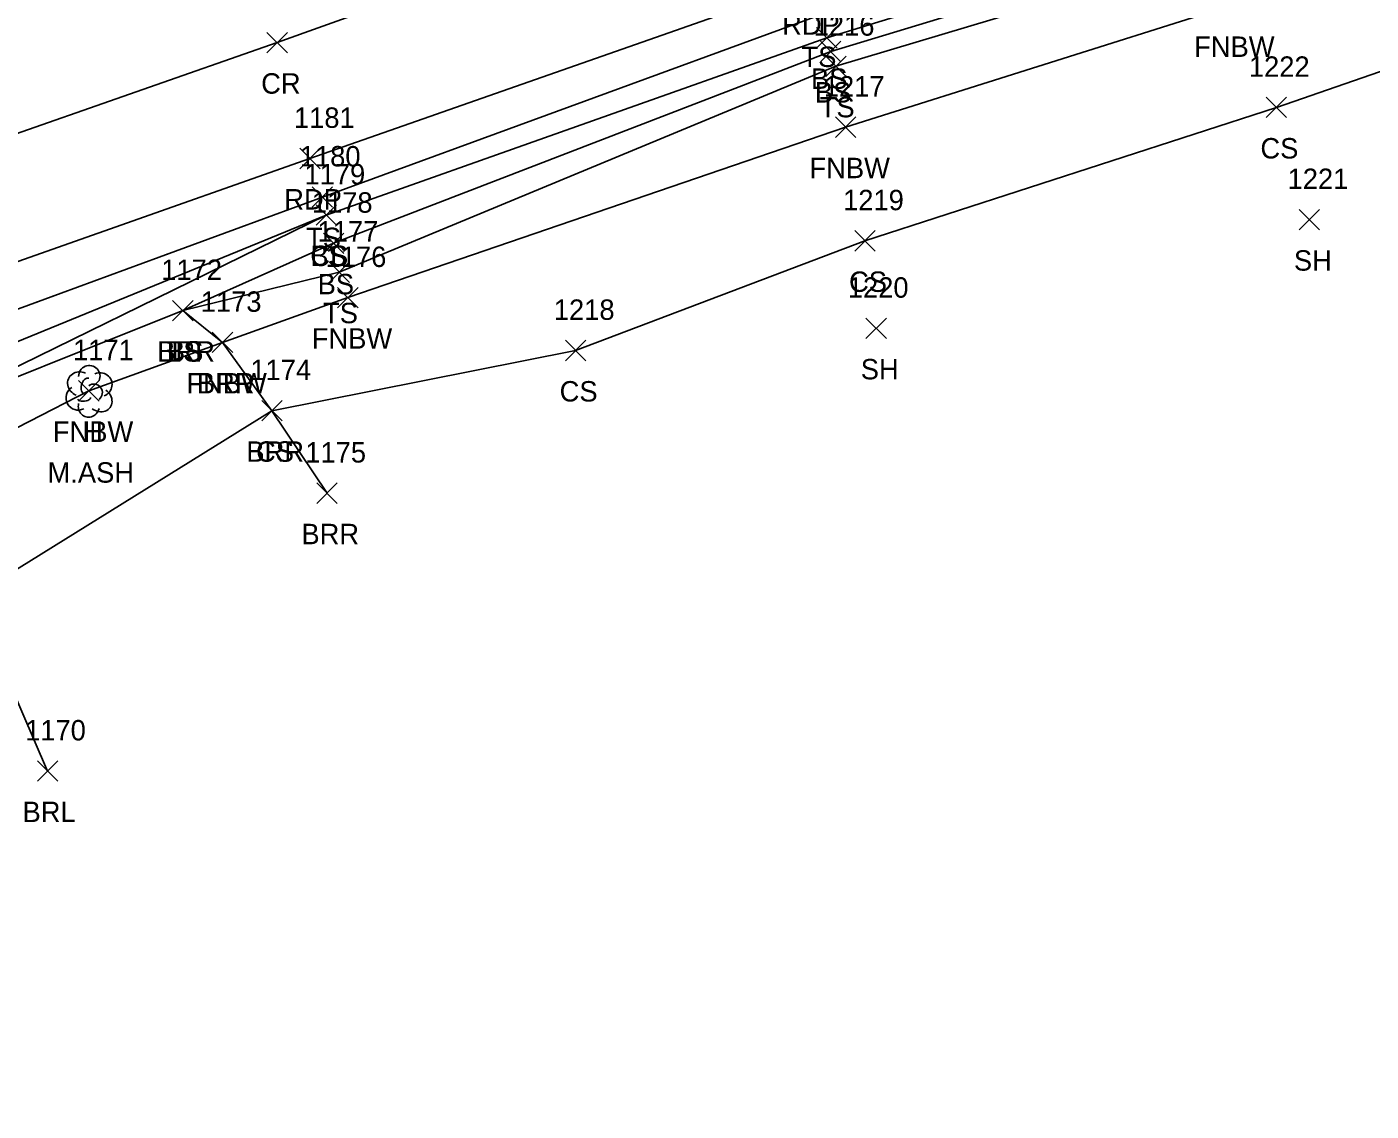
# Model space of a CAD drawing. Extents: x 1443064 to 1445163, y 544063 to 544655.
# Drawn here: x 1443332.1 to 1443463.7, y 544086.5 to 544192.7 of the extents above; entities that cross this region are included whole.
import ezdxf

# ---------------------------------------------------------------- set-up
doc = ezdxf.new("R2010")
doc.units = 0
for name, color, linetype in [('L_A', 7, 'Continuous'), ('L_C', 7, 'Continuous'), ('L_I', 7, 'Continuous'), ('L_TIC', 7, 'Continuous'), ('LABL', 7, 'Continuous'), ('LELB', 7, 'Continuous'), ('LFNC', 7, 'Continuous'), ('LTD', 7, 'Continuous'), ('P_A', 7, 'Continuous'), ('P_I', 7, 'Continuous'), ('P_TIC', 7, 'Continuous'), ('PET', 7, 'Continuous'), ('PRC', 7, 'Continuous')]:
    doc.layers.add(name, color=color, linetype=linetype)

msp = doc.modelspace()

# ---------------------------------------------------------------- linework, layer by layer
at = {"layer": 'L_TIC'}
for points in [[(1443409.41, 544190.66), (1443411.41, 544192.66)], [(1443411.41, 544190.66), (1443409.41, 544192.66)], [(1443409.79, 544189.32), (1443411.79, 544191.32)], [(1443411.79, 544189.32), (1443409.79, 544191.32)], [(1443410.3, 544187.87), (1443412.3, 544189.87)], [(1443412.3, 544187.87), (1443410.3, 544189.87)], [(1443453.43, 544183.84), (1443455.43, 544185.84)], [(1443455.43, 544183.84), (1443453.43, 544185.84)], [(1443411.24, 544181.91), (1443413.24, 544183.91)], [(1443413.24, 544181.91), (1443411.24, 544183.91)], [(1443360, 544175.06), (1443362, 544177.06)], [(1443362, 544175.06), (1443360, 544177.06)], [(1443360.38, 544173.3), (1443362.38, 544175.3)], [(1443362.38, 544173.3), (1443360.38, 544175.3)], [(1443360.38, 544173.3), (1443362.38, 544175.3)], [(1443362.38, 544173.3), (1443360.38, 544175.3)], [(1443456.66, 544172.85), (1443458.66, 544174.85)], [(1443458.66, 544172.85), (1443456.66, 544174.85)], [(1443361.1, 544170.53), (1443363.1, 544172.53)], [(1443363.1, 544170.53), (1443361.1, 544172.53)], [(1443413.14, 544170.77), (1443415.14, 544172.77)], [(1443415.14, 544170.77), (1443413.14, 544172.77)], [(1443361.66, 544167.7), (1443363.66, 544169.7)], [(1443363.66, 544167.7), (1443361.66, 544169.7)], [(1443362.5, 544165.21), (1443364.5, 544167.21)], [(1443364.5, 544165.21), (1443362.5, 544167.21)], [(1443346.34, 544163.94), (1443348.34, 544165.94)], [(1443348.34, 544163.94), (1443346.34, 544165.94)], [(1443346.34, 544163.94), (1443348.34, 544165.94)], [(1443348.34, 544163.94), (1443346.34, 544165.94)], [(1443346.34, 544163.94), (1443348.34, 544165.94)], [(1443348.34, 544163.94), (1443346.34, 544165.94)], [(1443414.24, 544162.2), (1443416.24, 544164.2)], [(1443416.24, 544162.2), (1443414.24, 544164.2)], [(1443350.22, 544160.82), (1443352.22, 544162.82)], [(1443352.22, 544160.82), (1443350.22, 544162.82)], [(1443350.22, 544160.82), (1443352.22, 544162.82)], [(1443352.22, 544160.82), (1443350.22, 544162.82)], [(1443384.8, 544160.03), (1443386.8, 544162.03)], [(1443386.8, 544160.03), (1443384.8, 544162.03)], [(1443337.13, 544156.08), (1443339.13, 544158.08)], [(1443339.13, 544156.08), (1443337.13, 544158.08)], [(1443355.07, 544154.13), (1443357.07, 544156.13)], [(1443357.07, 544154.13), (1443355.07, 544156.13)], [(1443355.07, 544154.13), (1443357.07, 544156.13)], [(1443357.07, 544154.13), (1443355.07, 544156.13)], [(1443360.46, 544146.05), (1443362.46, 544148.05)], [(1443362.46, 544146.05), (1443360.46, 544148.05)], [(1443333.1, 544118.83), (1443335.1, 544120.83)], [(1443335.1, 544118.83), (1443333.1, 544120.83)]]:
    msp.add_lwpolyline(points, dxfattribs=at)
at = {"layer": 'LABL'}
for points in [[(1443237.46, 544116.95), (1443239.88, 544119.45), (1443238.51, 544123.67), (1443277.41, 544137.07), (1443319.92, 544153.98), (1443347.34, 544164.94), (1443351.22, 544161.82), (1443356.07, 544155.13), (1443361.46, 544147.05)], [(1443237.46, 544116.95), (1443281.32, 544122.33), (1443313.89, 544135.8), (1443326.71, 544136.88), (1443334.1, 544119.83)]]:
    msp.add_lwpolyline(points, dxfattribs=at)
at = {"layer": 'LELB'}
for points in [[(1443082.68, 544086.51), (1443130.13, 544099.67), (1443144.13, 544104.98), (1443172.72, 544113.76), (1443212.83, 544125.42), (1443253.97, 544138.87), (1443319.39, 544160.76), (1443361, 544176.06), (1443409.52, 544193.8), (1443447.54, 544206.03), (1443485.93, 544218.99), (1443527.17, 544233.73), (1443570.65, 544246.93), (1443621.44, 544264.66), (1443656.15, 544276.08), (1443695.78, 544288.38), (1443720.36, 544296.79), (1443749.28, 544306.83), (1443759.63, 544310.57), (1443806.78, 544328.14), (1443835.8, 544338.24)], [(1443319.92, 544153.98), (1443361.38, 544174.3), (1443410.41, 544191.66), (1443447.48, 544203.1), (1443486.62, 544216.08), (1443527.2, 544231.22), (1443571.34, 544244.18), (1443622.82, 544261.27), (1443656.98, 544272.97), (1443695.69, 544285.56), (1443722.38, 544294.2), (1443748.12, 544301.75), (1443761.69, 544309.21), (1443807.82, 544325.32), (1443837.04, 544335.82)], [(1443347.34, 544164.94), (1443362.1, 544171.53), (1443410.79, 544190.32), (1443447.84, 544201.59), (1443487.26, 544214.65), (1443527.73, 544229.42), (1443571.89, 544241.52), (1443623.27, 544260), (1443657.62, 544270.44), (1443688.01, 544274.03), (1443701.05, 544275.03), (1443736.1, 544284.41), (1443746.14, 544291.27)], [(1443347.34, 544164.94), (1443362.66, 544168.7), (1443411.3, 544188.87), (1443447.45, 544199.71), (1443486.7, 544212.27), (1443529.19, 544224.77), (1443545.25, 544228.26), (1443571.88, 544240.98), (1443578.87, 544240.7)], [(1443326.71, 544136.88), (1443356.07, 544155.13), (1443385.8, 544161.03), (1443414.14, 544171.77), (1443454.43, 544184.84), (1443493.74, 544198.5), (1443535.62, 544210.92), (1443545.67, 544211.73), (1443551.85, 544201.5), (1443566.51, 544204.54), (1443590.28, 544210.64), (1443632.95, 544239.56)], [(1443194, 544113.59), (1443212.02, 544119.1), (1443220.44, 544121.4), (1443254.78, 544133.96), (1443275.08, 544141.94), (1443320.32, 544157.47), (1443361.38, 544174.3)]]:
    msp.add_lwpolyline(points, dxfattribs=at)
at = {"layer": 'LFNC'}
msp.add_lwpolyline([(1443239.88, 544119.45), (1443278.62, 544130.94), (1443320.57, 544148.06), (1443338.13, 544157.08), (1443351.22, 544161.82), (1443363.5, 544166.21), (1443412.24, 544182.91), (1443449.91, 544194.79), (1443489.63, 544207.22), (1443534.54, 544218.89), (1443545.24, 544222.13), (1443555.28, 544222.99), (1443566.76, 544221.91), (1443584.49, 544223.6), (1443632.95, 544239.56), (1443668.35, 544248.03), (1443707.08, 544263.81), (1443742.56, 544273.31)], dxfattribs=at)
at = {"layer": 'LTD'}
msp.add_line((1443338.13, 544157.08), (1443338.13, 544157.08), dxfattribs=at)
msp.add_line((1443338.13, 544157.08), (1443338.13, 544157.08), dxfattribs=at)
msp.add_arc((1443338.18, 544158.51), 1.05, 335.5272, 180.9563, dxfattribs=at)
for centre, major_axis, ratio, start_param, end_param in [((1443337.34, 544157.74), (1.21, -0.51), 0.895232, 1.570796, 4.712389), ((1443337.93, 544157.53), (-0.208, -0.792), 0.645439, 3.141593, 6.283185), ((1443339.18, 544157.66), (-1.14, -0.48), 0.949671, 1.570796, 4.712389), ((1443337.05, 544156.37), (0.58, -1.04), 0.959034, 3.141593, 6.283185), ((1443338.63, 544156.91), (-0.5, 0.667), 0.989748, 3.141593, 6.283185), ((1443339.13, 544156.24), (-1.09, 0.79), 0.841452, 1.570796, 4.712389), ((1443338.13, 544155.58), (0.26, 1.06), 0.942809, 1.570796, 4.712389), ((1443337.68, 544156.33), (-0.625, -0.083), 0.423636, 0, 3.141593)]:
    msp.add_ellipse(centre, major_axis=major_axis, ratio=ratio, start_param=start_param, end_param=end_param, dxfattribs=at)
at = {"layer": 'P_TIC'}
for points in [[(1443355.58, 544190.19), (1443357.58, 544192.19)], [(1443357.58, 544190.19), (1443355.58, 544192.19)], [(1443358.78, 544178.84), (1443360.78, 544180.84)], [(1443360.78, 544178.84), (1443358.78, 544180.84)]]:
    msp.add_lwpolyline(points, dxfattribs=at)
at = {"layer": 'PET'}
msp.add_lwpolyline([(1443081.93, 544089.54), (1443128.67, 544104.01), (1443173.03, 544117.15), (1443209.23, 544128.71), (1443253.49, 544142.88), (1443273.3, 544149.07), (1443318.27, 544165.2), (1443359.78, 544179.84), (1443408.54, 544196.96), (1443445.92, 544210.12), (1443484.92, 544223.61), (1443525.67, 544237.02), (1443568.63, 544251.04), (1443620.57, 544267.93), (1443654.52, 544278.93), (1443694.69, 544292.43), (1443717.24, 544299.44), (1443752.8, 544310.97), (1443757.72, 544314.31), (1443805.74, 544330.07), (1443835.35, 544341.18)], dxfattribs=at)
at = {"layer": 'PRC'}
msp.add_lwpolyline([(1443078.47, 544103.68), (1443125.02, 544115.93), (1443169.41, 544128.22), (1443204.47, 544139.4), (1443250.36, 544154.3), (1443269.99, 544160.83), (1443315.13, 544176.71), (1443356.58, 544191.19), (1443403.59, 544208.05), (1443442.67, 544222.02), (1443482.15, 544235.41), (1443522.16, 544248.37), (1443565.47, 544262.64), (1443616.51, 544279.34), (1443650.9, 544289.93), (1443689.58, 544302.53), (1443728.44, 544315.77), (1443753.53, 544324.68), (1443803.56, 544342.2), (1443830.96, 544352.16)], dxfattribs=at)

# ---------------------------------------------------------------- texts
at = {"layer": 'L_A'}
for s, p in [('FNBW', (1443446.38, 544189.79)), ('TS', (1443407.93, 544188.8)), ('BS', (1443408.86, 544186.66)), ('BS', (1443409.24, 544185.32)), ('TS', (1443409.71, 544183.87)), ('CS', (1443452.87, 544179.84)), ('FNBW', (1443408.71, 544177.91)), ('TS', (1443359.41, 544171.06)), ('CS', (1443359.82, 544169.3)), ('BS', (1443359.82, 544169.3)), ('SH', (1443456.15, 544168.85)), ('BS', (1443360.54, 544166.53)), ('CS', (1443412.58, 544166.77)), ('TS', (1443361.07, 544163.7)), ('FNBW', (1443359.97, 544161.21)), ('BRR', (1443344.83, 544159.94)), ('TS', (1443345.75, 544159.94)), ('BS', (1443345.78, 544159.94)), ('SH', (1443413.73, 544158.2)), ('FNBW', (1443347.69, 544156.82)), ('BRR', (1443348.71, 544156.82)), ('CS', (1443384.24, 544156.03)), ('FNBW', (1443334.61, 544152.08)), ('H', (1443337.57, 544152.08)), ('BRR', (1443353.56, 544150.13)), ('CS', (1443354.51, 544150.13)), ('BRR', (1443358.95, 544142.05)), ('BRL', (1443331.64, 544114.83))]:
    msp.add_text(s, height=2, dxfattribs=at).set_placement(p)
at = {"layer": 'L_C'}
msp.add_text('M.ASH', height=2, dxfattribs=at).set_placement((1443334.09, 544148.08))
at = {"layer": 'L_I'}
for s, p in [('1216', (1443409.12, 544191.87)), ('1222', (1443451.74, 544187.84)), ('1217', (1443410.11, 544185.91)), ('1180', (1443358.79, 544179.06)), ('1179', (1443359.25, 544177.3)), ('1179', (1443359.25, 544177.3)), ('1221', (1443455.53, 544176.85)), ('1219', (1443412, 544174.77)), ('1178', (1443359.97, 544174.53)), ('1177', (1443360.53, 544171.7)), ('1176', (1443361.32, 544169.21)), ('1172', (1443345.22, 544167.94)), ('1172', (1443345.22, 544167.94)), ('1172', (1443345.22, 544167.94)), ('1220', (1443412.46, 544166.2)), ('1173', (1443349.09, 544164.82)), ('1173', (1443349.09, 544164.82)), ('1218', (1443383.67, 544164.03)), ('1171', (1443336.58, 544160.08)), ('1171', (1443336.58, 544160.08)), ('1174', (1443353.95, 544158.13)), ('1174', (1443353.95, 544158.13)), ('1175', (1443359.33, 544150.05)), ('1170', (1443331.89, 544122.83))]:
    msp.add_text(s, height=2, dxfattribs=at).set_placement(p)
at = {"layer": 'P_A'}
for s, p in [('RDP', (1443406.03, 544191.96)), ('CR', (1443355.01, 544186.19)), ('RDP', (1443357.27, 544174.84))]:
    msp.add_text(s, height=2, dxfattribs=at).set_placement(p)
at = {"layer": 'P_I'}
msp.add_text('1181', height=2, dxfattribs=at).set_placement((1443358.22, 544182.84))

doc.saveas('drawing.dxf')
